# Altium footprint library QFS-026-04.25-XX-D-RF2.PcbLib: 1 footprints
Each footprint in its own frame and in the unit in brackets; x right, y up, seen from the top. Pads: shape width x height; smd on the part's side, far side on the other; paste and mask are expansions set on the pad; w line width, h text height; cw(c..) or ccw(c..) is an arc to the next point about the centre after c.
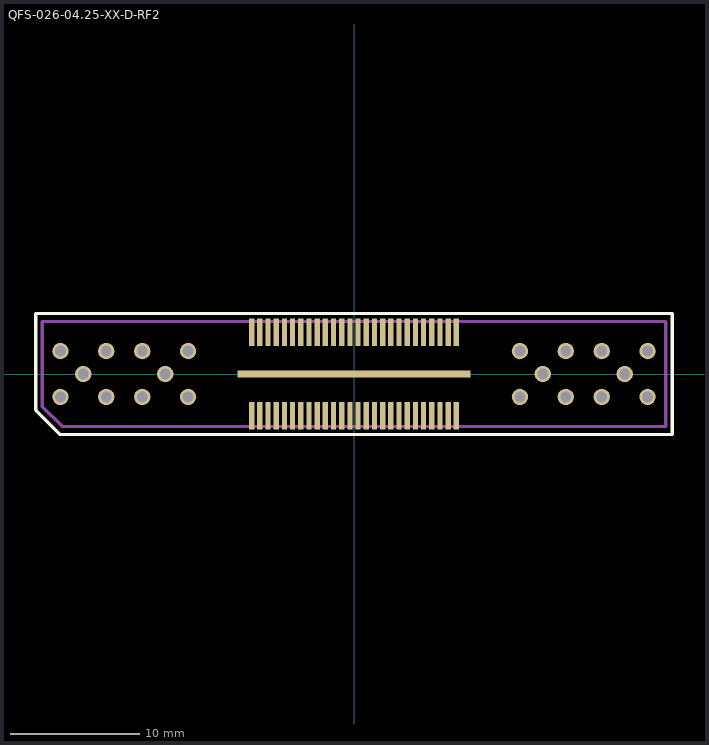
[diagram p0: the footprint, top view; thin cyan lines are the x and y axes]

## QFS-026-04.25-XX-D-RF2 [mil]
pads (73):
  rect 16x85 smd mask+2: 1(-312.5,127.5) 2(-312.5,-127.5) 3(-287.5,127.5) 4(-287.5,-127.5) 5(-262.5,127.5) 6(-262.5,-127.5) 7(-237.5,127.5) 8(-237.5,-127.5) 9(-212.5,127.5) 10(-212.5,-127.5) 11(-187.5,127.5) 12(-187.5,-127.5) 13(-162.5,127.5) 14(-162.5,-127.5) 15(-137.5,127.5) 16(-137.5,-127.5) 17(-112.5,127.5) 18(-112.5,-127.5) 19(-87.5,127.5) 20(-87.5,-127.5) 21(-62.5,127.5) 22(-62.5,-127.5) 23(-37.5,127.5) 24(-37.5,-127.5) 25(-12.5,127.5) 26(-12.5,-127.5) 27(12.5,127.5) 28(12.5,-127.5) 29(37.5,127.5) 30(37.5,-127.5) 31(62.5,127.5) 32(62.5,-127.5) 33(87.5,127.5) 34(87.5,-127.5) 35(112.5,127.5) 36(112.5,-127.5) 37(137.5,127.5) 38(137.5,-127.5) 39(162.5,127.5) 40(162.5,-127.5) 41(187.5,127.5) 42(187.5,-127.5) 43(212.5,127.5) 44(212.5,-127.5) 45(237.5,127.5) 46(237.5,-127.5) 47(262.5,127.5) 48(262.5,-127.5) 49(287.5,127.5) 50(287.5,-127.5) 51(312.5,127.5) 52(312.5,-127.5)
  rect 710x20 smd mask+2: 53(0,0)
  round 50 hole 33 mask+3: RF01-1(-826.5,0) RF01-2(-896.5,70) RF01-3(-756.5,70) RF01-4(-896.5,-70) RF01-5(-756.5,-70) RF02-1(-576.5,0) RF02-2(-646.5,70) RF02-3(-506.5,70) RF02-4(-646.5,-70) RF02-5(-506.5,-70) RF03-1(576.5,0) RF03-2(506.5,70) RF03-3(646.5,70) RF03-4(506.5,-70) RF03-5(646.5,-70) RF04-1(826.5,0) RF04-2(756.5,70) RF04-3(896.5,70) RF04-4(756.5,-70) RF04-5(896.5,-70)
Top Overlay:
  lines w10: -971.5,-110 -971.5,185 971.5,185 971.5,-185 -896.5,-185 -971.5,-110
Mechanical 1:
  lines w10: -951.5,-100 -951.5,160 951.5,160 951.5,-160 -891.5,-160 -951.5,-100
  text "J1" at -19.57,-20 h30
